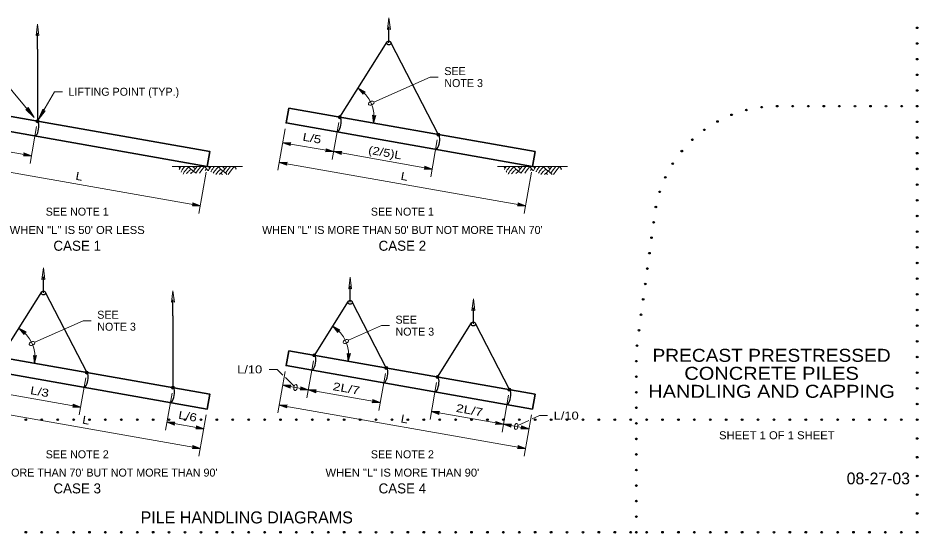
# Model space of a CAD drawing. Extents: x 99860 to 103153, y 99998 to 102077.
# Drawn here: x 101353 to 103152, y 99998 to 101029 of the extents above; entities that cross this region are included whole.
import ezdxf
from ezdxf.enums import TextEntityAlignment as Align

# ---------------------------------------------------------------- set-up
doc = ezdxf.new("R2010")
doc.units = 0
doc.header["$LTSCALE"] = 6.4
doc.header["$PDMODE"] = 32
doc.header["$PDSIZE"] = 3.2
for name, color, linetype in [('1', 7, 'Continuous'), ('61', 7, 'Continuous'), ('62', 7, 'Continuous')]:
    doc.layers.add(name, color=color, linetype=linetype)
for name, color, linetype, lineweight in [('15', 7, 'Continuous', 13), ('17', 7, 'Continuous', 13), ('18', 7, 'Continuous', 25), ('20', 7, 'Continuous', 13)]:
    doc.layers.add(name, color=color, linetype=linetype, lineweight=lineweight)

msp = doc.modelspace()

# ---------------------------------------------------------------- hatches: boundary and pattern name
at = {"layer": '15'}
for points in [[(102032.349, 100888.359), (102046.583, 100880.999), (102044.095, 100879.035), (102042.75, 100876.167)], [(101393.021, 100824.692), (101407.02, 100842.97), (101403.906, 100843.546), (101401.85, 100845.955)], [(101394.563, 100822.022, 1), (101388.395, 100822.022, 1)], [(101998.77, 100830.096, 1), (101992.602, 100830.096, 1)], [(102063.478, 100818.142), (102067.582, 100833.632), (102064.457, 100833.107), (102061.428, 100834.036)], [(102195.731, 100795.367, 1), (102189.563, 100795.367, 1)], [(101881.603, 100779.132), (101896.554, 100773.364), (101896.372, 100776.528), (101897.625, 100779.439)], [(101379.324, 100753.087), (101364.374, 100758.854), (101364.555, 100755.691), (101363.303, 100752.78)], [(101983.531, 100761.16), (101968.58, 100766.927), (101968.761, 100763.764), (101967.509, 100760.853)], [(101983.531, 100761.16), (101998.481, 100755.392), (101998.3, 100758.555), (101999.552, 100761.466)], [(101874.657, 100739.74), (101889.608, 100733.972), (101889.426, 100737.136), (101890.679, 100740.046)], [(102180.492, 100726.43), (102165.542, 100732.198), (102165.723, 100729.034), (102164.47, 100726.123)], [(101717.061, 100652.917), (101702.111, 100658.685), (101702.292, 100655.522), (101701.04, 100652.611)], [(102367.061, 100652.916), (102352.11, 100658.683), (102352.292, 100655.52), (102351.039, 100652.609)], [(101354.282, 100407.973), (101368.516, 100400.613), (101366.028, 100398.649), (101364.683, 100395.781)], [(101981.631, 100411.967), (101995.865, 100404.607), (101993.377, 100402.643), (101992.032, 100399.775)], [(101385.411, 100337.756), (101389.515, 100353.246), (101386.39, 100352.721), (101383.361, 100353.65)], [(101948.052, 100353.704, 1), (101941.884, 100353.704, 1)], [(102012.76, 100341.75), (102016.864, 100357.24), (102013.739, 100356.715), (102010.71, 100357.644)], [(101493.044, 100319.322, 1), (101486.876, 100319.322, 1)], [(102091.834, 100328.351, 1), (102085.666, 100328.351, 1)], [(102194.254, 100310.292, 1), (102188.086, 100310.292, 1)], [(101665.385, 100288.933, 1), (101659.217, 100288.933, 1)], [(101881.603, 100293.798), (101896.554, 100288.03), (101896.372, 100291.194), (101897.625, 100294.104)], [(101932.813, 100284.768), (101917.863, 100290.536), (101918.044, 100287.372), (101916.792, 100284.462)], [(101932.813, 100284.768), (101947.764, 100279), (101947.582, 100282.164), (101948.835, 100285.075)], [(102338.036, 100284.939, 1), (102331.868, 100284.939, 1)], [(102076.595, 100259.416), (102061.645, 100265.183), (102061.826, 100262.02), (102060.574, 100259.109)], [(101477.805, 100250.386), (101462.854, 100256.154), (101463.036, 100252.99), (101461.783, 100250.08)], [(101874.657, 100254.406), (101889.608, 100248.638), (101889.426, 100251.801), (101890.679, 100254.712)], [(102179.014, 100241.356), (102195.036, 100241.663), (102193.783, 100238.752), (102193.965, 100235.589)], [(101650.146, 100219.997), (101665.097, 100214.229), (101664.915, 100217.393), (101666.168, 100220.303)], [(101724.007, 100206.974), (101709.056, 100212.742), (101709.238, 100209.578), (101707.985, 100206.668)], [(102322.796, 100216.004), (102306.774, 100215.697), (102308.027, 100218.608), (102307.846, 100221.771)], [(102322.796, 100216.004), (102338.818, 100216.31), (102337.565, 100213.4), (102337.747, 100210.236)], [(102374.006, 100206.974), (102357.984, 100206.667), (102359.237, 100209.578), (102359.056, 100212.742)], [(101717.061, 100167.582), (101702.11, 100173.35), (101702.292, 100170.186), (101701.039, 100167.275)], [(102367.061, 100167.582), (102352.111, 100173.349), (102352.292, 100170.186), (102351.04, 100167.275)]]:
    msp.add_hatch(color=256, dxfattribs=at).paths.add_polyline_path(points)
at = {"layer": '18'}
for points in [[(102093.819, 101028.531), (102096.804, 101005.702), (102093.819, 101006.758), (102090.834, 101005.701)], [(101391.479, 101016.028), (101394.464, 100993.199), (101391.479, 100994.255), (101388.494, 100993.198)], [(101403.442, 100528.583), (101406.427, 100505.754), (101403.442, 100506.81), (101400.457, 100505.753)], [(102016.512, 100509.885), (102019.497, 100487.056), (102016.512, 100488.112), (102013.527, 100487.055)], [(101662.301, 100482.939), (101665.286, 100460.11), (101662.301, 100461.166), (101659.316, 100460.109)], [(102262.714, 100466.473), (102265.699, 100443.644), (102262.714, 100444.7), (102259.729, 100443.643)]]:
    msp.add_hatch(color=256, dxfattribs=at).paths.add_polyline_path(points)
at = {"layer": '20'}
msp.add_hatch(color=256, dxfattribs=at).paths.add_polyline_path([(101384.947, 100829.805), (101372.56, 100849.212), (101370.952, 100846.484), (101367.986, 100845.375)])

# ---------------------------------------------------------------- linework, layer by layer
at = {"layer": '1'}
for p in [(103149.998, 101008.898), (103149.998, 100977.542), (103149.998, 100946.186), (103149.998, 100914.83), (103149.998, 100883.475), (102808.474, 100844.385), (102839.012, 100850.195), (102870.038, 100852.119), (102901.145, 100852.119), (102932.251, 100852.119), (102963.358, 100852.119), (102994.465, 100852.119), (103025.572, 100852.119), (103056.678, 100852.119), (103087.785, 100852.119), (103118.892, 100852.119), (103149.998, 100852.119), (102750.796, 100821.514), (102778.912, 100834.774), (103149.998, 100820.763), (102724.576, 100804.817), (102700.668, 100784.949), (103149.998, 100789.407), (102679.455, 100762.227), (103149.998, 100758.051), (102661.274, 100737.013), (103149.998, 100726.695), (102646.414, 100709.709), (103149.998, 100695.339), (102635.114, 100680.75), (103149.998, 100663.983), (102627.553, 100650.599), (103149.998, 100632.627), (102623.09, 100619.817), (102618.916, 100588.992), (103149.998, 100601.271), (103149.998, 100569.915), (102614.742, 100558.166), (103149.998, 100538.559), (102610.569, 100527.341), (102606.395, 100496.516), (103149.998, 100507.203), (102602.221, 100465.69), (103149.998, 100475.847), (103149.998, 100444.491), (102598.047, 100434.865), (103149.998, 100413.136), (102593.873, 100404.039), (102589.699, 100373.214), (103149.998, 100381.78), (102588.709, 100342.174), (103149.998, 100350.424), (103149.998, 100319.068), (102588.709, 100311.067), (102588.709, 100279.96), (103149.998, 100287.712), (102588.709, 100248.854), (103149.998, 100256.356), (101368.181, 100225), (101400, 100225), (101431.818, 100225), (101463.636, 100225), (101495.454, 100225), (101527.272, 100225), (101559.09, 100225), (101590.909, 100225), (101622.727, 100225), (101654.545, 100225), (101686.363, 100225), (101718.181, 100225), (101749.999, 100225), (101781.818, 100225), (101813.636, 100225), (101845.454, 100225), (101877.272, 100225), (101909.09, 100225), (101940.908, 100225), (101972.726, 100225), (102004.545, 100225), (102036.363, 100225), (102068.181, 100225), (102099.999, 100225), (102131.817, 100225), (102163.635, 100225), (102195.454, 100225), (102227.272, 100225), (102259.09, 100225), (102290.908, 100225), (102322.726, 100225), (102354.544, 100225), (102386.363, 100225), (102418.181, 100225), (102449.999, 100225), (102481.817, 100225), (102513.635, 100225), (102545.453, 100225), (102577.272, 100225), (102588.709, 100217.747), (102609.09, 100225), (102640.908, 100225), (102672.726, 100225), (102704.544, 100225), (102736.362, 100225), (102768.181, 100225), (102799.999, 100225), (102831.817, 100225), (102863.635, 100225), (102895.453, 100225), (102927.271, 100225), (102959.09, 100225), (102990.908, 100225), (103022.726, 100225), (103054.544, 100225), (103086.362, 100225), (103118.18, 100225), (103149.998, 100225), (102588.709, 100186.64), (103149.998, 100187.5), (102588.709, 100155.534), (103149.998, 100150), (102588.709, 100124.427), (103149.998, 100112.5), (102588.709, 100093.32), (103149.998, 100075), (102588.709, 100062.213), (102588.709, 100031.107), (103149.998, 100037.5), (101368.181, 100000), (101400, 100000), (101431.818, 100000), (101463.636, 100000), (101495.454, 100000), (101527.272, 100000), (101559.09, 100000), (101590.909, 100000), (101622.727, 100000), (101654.545, 100000), (101686.363, 100000), (101718.181, 100000), (101749.999, 100000), (101781.818, 100000), (101813.636, 100000), (101845.454, 100000), (101877.272, 100000), (101909.09, 100000), (101940.908, 100000), (101972.726, 100000), (102004.545, 100000), (102036.363, 100000), (102068.181, 100000), (102099.999, 100000), (102131.817, 100000), (102163.635, 100000), (102195.454, 100000), (102227.272, 100000), (102259.09, 100000), (102290.908, 100000), (102322.726, 100000), (102354.544, 100000), (102386.363, 100000), (102418.181, 100000), (102449.999, 100000), (102481.817, 100000), (102513.635, 100000), (102545.453, 100000), (102577.272, 100000), (102588.709, 100000), (102609.09, 100000), (102640.908, 100000), (102672.726, 100000), (102704.544, 100000), (102736.362, 100000), (102768.181, 100000), (102799.999, 100000), (102831.817, 100000), (102863.635, 100000), (102895.453, 100000), (102927.271, 100000), (102959.09, 100000), (102990.908, 100000), (103022.726, 100000), (103054.544, 100000), (103086.362, 100000), (103118.18, 100000), (103149.998, 100000)]:
    msp.add_point(p, dxfattribs=at)
at = {"layer": '15'}
for p, q in [((102064.101, 100860.427), (102176.69, 100910.341)), ((102176.689, 100910.341), (102192.688, 100910.341)), ((101393.021, 100824.692), (101425.521, 100880.983)), ((101425.521, 100880.984), (101441.521, 100880.984)), ((101389.569, 100811.189), (101376.545, 100737.328)), ((101886.465, 100806.707), (101871.878, 100723.983)), ((101993.776, 100819.263), (101980.752, 100745.403)), ((101231.603, 100779.132), (101379.324, 100753.085)), ((101881.603, 100779.132), (101983.53, 100761.16)), ((102190.737, 100784.534), (102177.713, 100710.673)), ((101983.53, 100761.16), (102180.492, 100726.43)), ((101224.657, 100739.74), (101717.061, 100652.916)), ((101660.952, 100731.7), (101800.952, 100731.7)), ((101874.657, 100739.74), (102367.061, 100652.916)), ((102310.952, 100731.7), (102450.952, 100731.7)), ((101728.869, 100719.883), (101714.282, 100637.159)), ((102378.869, 100719.883), (102364.282, 100637.159)), ((101386.034, 100380.041), (101482.904, 100422.986)), ((101482.903, 100422.986), (101498.902, 100422.986)), ((102013.384, 100384.035), (102079.087, 100413.163)), ((102079.086, 100413.163), (102095.085, 100413.163)), ((101943.058, 100342.871), (101930.034, 100269.01)), ((101854.834, 100325.656), (101870.834, 100325.656)), ((101882.174, 100314.316), (101870.834, 100325.656)), ((101886.465, 100321.372), (101871.878, 100238.648)), ((101488.05, 100308.489), (101475.026, 100234.628)), ((101904.435, 100292.055), (101887.354, 100309.136)), ((102086.84, 100317.518), (102073.816, 100243.658)), ((101881.603, 100293.797), (101932.813, 100284.767)), ((101932.813, 100284.767), (102076.595, 100259.415)), ((102189.26, 100299.459), (102176.236, 100225.598)), ((101305.463, 100280.773), (101477.805, 100250.385)), ((101660.391, 100278.1), (101647.368, 100204.24)), ((102333.042, 100274.106), (102320.018, 100200.246)), ((101224.657, 100254.405), (101717.061, 100167.581)), ((101874.657, 100254.405), (102367.061, 100167.581)), ((101728.869, 100234.548), (101714.282, 100151.824)), ((102322.797, 100216.003), (102179.015, 100241.355)), ((102378.869, 100234.548), (102364.282, 100151.824)), ((102380.487, 100226.45), (102395.022, 100233.227)), ((102395.022, 100233.228), (102411.022, 100233.228)), ((101724.006, 100206.972), (101650.146, 100219.996)), ((102374.007, 100206.973), (102322.797, 100216.003)), ((102351.955, 100213.145), (102373.849, 100223.354))]:
    msp.add_line(p, q, dxfattribs=at)
for points in [[(102032.349, 100888.359), (102046.583, 100880.999), (102044.095, 100879.035), (102042.75, 100876.167)], [(101393.021, 100824.692), (101407.02, 100842.97), (101403.906, 100843.546), (101401.85, 100845.955)], [(102063.478, 100818.142), (102067.582, 100833.632), (102064.457, 100833.107), (102061.428, 100834.036)], [(101881.603, 100779.132), (101896.554, 100773.364), (101896.372, 100776.528), (101897.625, 100779.439)], [(101379.324, 100753.087), (101364.374, 100758.854), (101364.555, 100755.691), (101363.303, 100752.78)], [(101983.531, 100761.16), (101968.58, 100766.927), (101968.761, 100763.764), (101967.509, 100760.853)], [(101983.531, 100761.16), (101998.481, 100755.392), (101998.3, 100758.555), (101999.552, 100761.466)], [(101874.657, 100739.74), (101889.608, 100733.972), (101889.426, 100737.136), (101890.679, 100740.046)], [(102180.492, 100726.43), (102165.542, 100732.198), (102165.723, 100729.034), (102164.47, 100726.123)], [(101717.061, 100652.917), (101702.111, 100658.685), (101702.292, 100655.522), (101701.04, 100652.611)], [(102367.061, 100652.916), (102352.11, 100658.683), (102352.292, 100655.52), (102351.039, 100652.609)], [(101354.282, 100407.973), (101368.516, 100400.613), (101366.028, 100398.649), (101364.683, 100395.781)], [(101981.631, 100411.967), (101995.865, 100404.607), (101993.377, 100402.643), (101992.032, 100399.775)], [(101385.411, 100337.756), (101389.515, 100353.246), (101386.39, 100352.721), (101383.361, 100353.65)], [(102012.76, 100341.75), (102016.864, 100357.24), (102013.739, 100356.715), (102010.71, 100357.644)], [(101881.603, 100293.798), (101896.554, 100288.03), (101896.372, 100291.194), (101897.625, 100294.104)], [(101932.813, 100284.768), (101917.863, 100290.536), (101918.044, 100287.372), (101916.792, 100284.462)], [(101932.813, 100284.768), (101947.764, 100279), (101947.582, 100282.164), (101948.835, 100285.075)], [(102076.595, 100259.416), (102061.645, 100265.183), (102061.826, 100262.02), (102060.574, 100259.109)], [(101477.805, 100250.386), (101462.854, 100256.154), (101463.036, 100252.99), (101461.783, 100250.08)], [(101874.657, 100254.406), (101889.608, 100248.638), (101889.426, 100251.801), (101890.679, 100254.712)], [(102179.014, 100241.356), (102195.036, 100241.663), (102193.783, 100238.752), (102193.965, 100235.589)], [(101650.146, 100219.997), (101665.097, 100214.229), (101664.915, 100217.393), (101666.168, 100220.303)], [(101724.007, 100206.974), (101709.056, 100212.742), (101709.238, 100209.578), (101707.985, 100206.668)], [(102322.796, 100216.004), (102306.774, 100215.697), (102308.027, 100218.608), (102307.846, 100221.771)], [(102322.796, 100216.004), (102338.818, 100216.31), (102337.565, 100213.4), (102337.747, 100210.236)], [(102374.006, 100206.974), (102357.984, 100206.667), (102359.237, 100209.578), (102359.056, 100212.742)], [(101717.061, 100167.582), (101702.11, 100173.35), (101702.292, 100170.186), (101701.039, 100167.275)], [(102367.061, 100167.582), (102352.111, 100173.349), (102352.292, 100170.186), (102351.04, 100167.275)]]:
    msp.add_lwpolyline(points, close=True, dxfattribs=at)
for centre in [(101391.479, 100822.022), (101995.686, 100830.096), (102192.647, 100795.367), (101944.968, 100353.704), (101489.96, 100319.322), (102088.75, 100328.351), (102191.17, 100310.292), (101662.301, 100288.933), (102334.952, 100284.939)]:
    msp.add_circle(centre, 3.084, dxfattribs=at)
for centre in [(101995.686, 100830.096), (101317.619, 100349.71), (101944.968, 100353.704)]:
    msp.add_arc(centre, 68.838, 350, 57.81849, dxfattribs=at)
for centre, major_axis in [((102058.616, 100857.995), (-5.485, -2.432)), ((101380.549, 100377.609), (-5.485, -2.432)), ((102007.899, 100381.603), (-5.485, -2.432)), ((101907.208, 100289.282), (-1.042, -5.909)), ((102348.402, 100211.488), (-1.042, -5.909))]:
    msp.add_ellipse(centre, major_axis=major_axis, ratio=0.57735, dxfattribs=at)
at = {"layer": '17'}
for p, q in [((101673.784, 100731.7), (101676.275, 100728.378)), ((101703.298, 100722.045), (101710.54, 100731.7)), ((101710.723, 100722.045), (101717.965, 100731.7)), ((101718.147, 100722.045), (101725.389, 100731.7)), ((101725.755, 100731.7), (101731.8, 100723.64)), ((101733.18, 100731.7), (101735.671, 100728.378)), ((101762.694, 100722.045), (101769.936, 100731.7)), ((101770.119, 100722.045), (101777.361, 100731.7)), ((101777.543, 100722.045), (101784.785, 100731.7)), ((101785.151, 100731.7), (101788.742, 100726.913)), ((101792.576, 100731.7), (101792.693, 100731.544)), ((102323.784, 100731.7), (102326.275, 100728.378)), ((102353.298, 100722.045), (102360.54, 100731.7)), ((102360.723, 100722.045), (102367.965, 100731.7)), ((102368.147, 100722.045), (102375.389, 100731.7)), ((102375.755, 100731.7), (102381.8, 100723.64)), ((102383.18, 100731.7), (102385.671, 100728.378)), ((102412.694, 100722.045), (102419.936, 100731.7)), ((102420.119, 100722.045), (102427.361, 100731.7)), ((102427.543, 100722.045), (102434.785, 100731.7)), ((102435.151, 100731.7), (102438.742, 100726.913)), ((102442.576, 100731.7), (102442.693, 100731.544)), ((101707.952, 100718.351), (101710.723, 100722.045)), ((101715.399, 100718.38), (101718.147, 100722.045)), ((101726.695, 100723.542), (101729.284, 100726.995)), ((101767.348, 100718.351), (101770.119, 100722.045)), ((101772.692, 100715.576), (101777.543, 100722.045)), ((101787.73, 100725.727), (101788.68, 100726.995)), ((102357.952, 100718.351), (102360.723, 100722.045)), ((102365.399, 100718.38), (102368.147, 100722.045)), ((102376.695, 100723.542), (102379.284, 100726.995)), ((102417.348, 100718.351), (102420.119, 100722.045)), ((102422.692, 100715.576), (102427.543, 100722.045)), ((102437.73, 100725.727), (102438.68, 100726.995))]:
    msp.add_line(p, q, dxfattribs=at)
for centre, start, end in [((101709.411, 100710.655), 145.94104, 156.43679), ((101713.123, 100705.706), 136.22985, 154.2266), ((101724.26, 100753.233), 214.96132, 236.09639), ((101727.972, 100758.183), 224.80891, 228.95992), ((101768.807, 100710.655), 145.94104, 160.98329), ((101772.519, 100705.706), 136.22985, 154.2266), ((101783.656, 100753.233), 214.96132, 236.09639), ((101787.368, 100758.183), 224.80891, 228.95992), ((102359.411, 100710.655), 145.94104, 156.43679), ((102363.123, 100705.706), 136.22985, 154.2266), ((102374.26, 100753.233), 214.96132, 236.09639), ((102377.972, 100758.183), 224.80891, 228.95992), ((102418.807, 100710.655), 145.94104, 160.98329), ((102422.519, 100705.706), 136.22985, 154.2266), ((102433.656, 100753.233), 214.96132, 236.09639), ((102437.368, 100758.183), 224.80891, 228.95992), ((101713.123, 100705.706), 154.22654, 157.7186), ((101716.835, 100700.756), 145.49102, 155.61297), ((101716.835, 100700.756), 127.1006, 145.49109), ((101720.547, 100695.806), 135.71269, 146.21381), ((101720.547, 100695.806), 126.331, 135.71278), ((101724.26, 100690.856), 123.90361, 135.4279), ((101678.626, 100685.907), 56.77068, 58.54646), ((101727.971, 100758.183), 228.95986, 236.09639), ((101682.338, 100690.856), 46.09335, 56.09634), ((101772.519, 100705.706), 154.22654, 156.74543), ((101776.231, 100700.756), 145.49102, 152.52576), ((101776.231, 100700.756), 127.1006, 145.49109), ((101779.943, 100695.806), 135.71269, 148.30119), ((101779.943, 100695.806), 126.331, 135.71278), ((101783.656, 100690.856), 123.90361, 139.15983), ((101738.022, 100685.907), 51.90593, 58.54646), ((101787.367, 100758.183), 228.95986, 236.09639), ((101741.734, 100690.856), 41.08977, 56.09634), ((102363.123, 100705.706), 154.22654, 157.7186), ((102366.835, 100700.756), 145.49102, 155.61297), ((102366.835, 100700.756), 127.1006, 145.49109), ((102370.547, 100695.806), 135.71269, 146.21381), ((102370.547, 100695.806), 126.331, 135.71278), ((102374.26, 100690.856), 123.90361, 135.4279), ((102328.626, 100685.907), 56.77068, 58.54646), ((102377.971, 100758.183), 228.95986, 236.09639), ((102332.338, 100690.856), 46.09335, 56.09634), ((102422.519, 100705.706), 154.22654, 156.74543), ((102426.231, 100700.756), 145.49102, 152.52576), ((102426.231, 100700.756), 127.1006, 145.49109), ((102429.943, 100695.806), 135.71269, 148.30119), ((102429.943, 100695.806), 126.331, 135.71278), ((102433.656, 100690.856), 123.90361, 139.15983), ((102388.022, 100685.907), 51.90593, 58.54646), ((102437.367, 100758.183), 228.95986, 236.09639), ((102391.734, 100690.856), 41.08977, 56.09634)]:
    msp.add_arc(centre, 37.577, start, end, dxfattribs=at)
at = {"layer": '18'}
for p, q in [((102093.819, 100978.531), (102093.819, 101010.662)), ((101391.479, 100966.027), (101391.479, 100998.158)), ((101391.479, 100966.027), (101391.479, 100822.022)), ((101995.686, 100830.096), (102090.434, 100980.661)), ((102097.375, 100980.362), (102192.647, 100795.367)), ((101403.442, 100478.583), (101403.442, 100510.714)), ((101317.619, 100349.71), (101400.057, 100480.713)), ((101406.998, 100480.414), (101489.96, 100319.322)), ((102016.512, 100459.884), (102016.512, 100492.015)), ((101662.301, 100432.939), (101662.301, 100465.07)), ((101944.968, 100353.704), (102013.126, 100462.015)), ((102020.068, 100461.716), (102088.75, 100328.351)), ((102262.714, 100416.472), (102262.714, 100448.603)), ((101662.301, 100432.939), (101662.301, 100288.933)), ((102191.17, 100310.292), (102259.328, 100418.603)), ((102266.27, 100418.304), (102334.952, 100284.939))]:
    msp.add_line(p, q, dxfattribs=at)
at = {"layer": '18', "lineweight": 13}
for points in [[(102093.819, 101028.531), (102096.804, 101005.702), (102093.819, 101006.758), (102090.834, 101005.701)], [(101391.479, 101016.028), (101394.464, 100993.199), (101391.479, 100994.255), (101388.494, 100993.198)], [(101403.442, 100528.583), (101406.427, 100505.754), (101403.442, 100506.81), (101400.457, 100505.753)], [(102016.512, 100509.885), (102019.497, 100487.056), (102016.512, 100488.112), (102013.527, 100487.055)], [(101662.301, 100482.939), (101665.286, 100460.11), (101662.301, 100461.166), (101659.316, 100460.109)], [(102262.714, 100466.473), (102265.699, 100443.644), (102262.714, 100444.7), (102259.729, 100443.643)]]:
    msp.add_lwpolyline(points, close=True, dxfattribs=at)
at = {"layer": '18', "lineweight": 35}
for points in [[(101243.758, 100848.069), (101736.162, 100761.245), (101730.952, 100731.7), (101238.549, 100818.525)], [(101893.758, 100848.069), (102386.162, 100761.245), (102380.952, 100731.7), (101888.549, 100818.525)], [(101243.758, 100362.734), (101736.162, 100275.91), (101730.952, 100246.365), (101238.549, 100333.189)], [(101893.758, 100362.734), (102386.162, 100275.91), (102380.952, 100246.365), (101888.549, 100333.189)]]:
    msp.add_lwpolyline(points, close=True, dxfattribs=at)
at = {"layer": '18'}
for centre in [(102093.819, 100978.531), (101403.442, 100478.583), (102016.512, 100459.884), (102262.714, 100416.472)]:
    msp.add_circle(centre, 4, dxfattribs=at)
for centre in [(101388.874, 100807.249), (101993.081, 100815.324), (102190.042, 100780.594), (101942.363, 100338.932), (101487.355, 100304.549), (102086.145, 100313.579), (102188.565, 100295.52), (101659.697, 100274.161), (102332.347, 100270.167)]:
    msp.add_ellipse(centre, major_axis=(2.605, 14.772), ratio=0.333333, start_param=3.14159265, end_param=6.28318531, dxfattribs=at)
at = {"layer": '20'}
msp.add_line((101384.948, 100829.805), (101323.326, 100903.243), dxfattribs=at)
msp.add_lwpolyline([(101384.947, 100829.805), (101372.56, 100849.212), (101370.952, 100846.484), (101367.986, 100845.375)], close=True, dxfattribs=at)

# ---------------------------------------------------------------- texts
for s, p in [('SEE', (102204.694, 100914.347)), ('NOTE 3', (102204.694, 100890.346)), ('LIFTING POINT (TYP.)', (101453.526, 100872.986)), ('SEE', (101510.906, 100426.991)), ('SEE', (102107.089, 100417.166)), ('NOTE 3', (101510.906, 100402.99)), ('NOTE 3', (102107.089, 100393.165))]:
    msp.add_text(s, height=16, dxfattribs=at).set_placement(p)
for s, width, p in [('L/5', 1.25, (101938.896, 100780.266)), ('(2/5)L', 1.2, (102084.793, 100751.431)), ('L', 1.2, (101473.641, 100703.963)), ('L', 1.2, (102123.64, 100703.963)), ('2L/7', 1.3, (102007.488, 100279.729)), ('L/3', 1.25, (101394.417, 100273.215)), ('2L/7', 1.3, (102253.69, 100236.316)), ('L', 1.2, (101486.989, 100216.275)), ('L/6', 1.25, (101690.391, 100224.137)), ('L', 1.2, (102123.642, 100218.63))]:
    msp.add_text(s, height=16, rotation=350, dxfattribs=dict(at, width=width)).set_placement(p, align=Align.CENTER)
for s, height, p in [('SEE NOTE 1', 16, (101470.86, 100633.201)), ('SEE NOTE 1', 16, (102120.86, 100633.2)), ('WHEN "L" IS MORE THAN 50\' BUT NOT MORE THAN 70\'', 16, (102120.86, 100596.564)), ('CASE 1', 20, (101470.86, 100562.927)), ('CASE 2', 20, (102120.86, 100562.927)), ('SEE NOTE 2', 16, (101470.86, 100147.865)), ('SEE NOTE 2', 16, (102120.86, 100147.865)), ('WHEN "L" IS MORE THAN 70\' BUT NOT MORE THAN 90\'', 16, (101470.86, 100111.229)), ('CASE 3', 20, (101470.86, 100077.593)), ('CASE 4', 20, (102120.86, 100077.593)), ('PILE HANDLING DIAGRAMS', 24, (101809.753, 100017.59))]:
    msp.add_text(s, height=height, dxfattribs=at).set_placement(p, align=Align.CENTER)
for s, width, p in [('WHEN "L" IS 50\' OR LESS', 1.05, (101470.86, 100596.564)), ('L/10', 1.2, (101815.663, 100317.658)), ('L/10', 1.2, (102448.373, 100225.229)), ('WHEN "L" IS MORE THAN 90\'', 1.05, (102120.86, 100111.229))]:
    msp.add_text(s, height=16, dxfattribs=dict(at, width=width)).set_placement(p, align=Align.CENTER)
at = {"layer": '61'}
msp.add_text('08-27-03', height=23.62, dxfattribs=at).set_placement((103072.261, 100095.777), align=Align.CENTER)
at = {"layer": '62'}
for s, height, width, p in [('PRECAST PRESTRESSED', 26, 1.1, (102858.885, 100340.801)), ('CONCRETE PILES', 26, 1.15, (102858.886, 100304.801)), ('HANDLING AND CAPPING', 26, 1.15, (102858.886, 100268.802)), ('SHEET 1 OF 1 SHEET', 16, 1.05, (102869.355, 100185.938))]:
    msp.add_text(s, height=height, dxfattribs=dict(at, width=width)).set_placement(p, align=Align.CENTER)

doc.saveas('drawing.dxf')
